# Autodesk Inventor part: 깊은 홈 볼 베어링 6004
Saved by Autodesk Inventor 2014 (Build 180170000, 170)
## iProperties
Created: 2026-04
Part Number: 깊은 홈 볼 베어링 6004
Material: 강철, 연강
Document SubType Name: Modeling
Designer: dg
Density: 7.86 g/cm^3
Appearance: 강철
Mass: 68.3136 g
Surface Area: 70.0178 cm^2
Volume: 8.6913 cm^3
Author: jhkim
Description: 깊은 그루브 볼 베어링
Creation Date: 2026-03-27
Sending System: Autodesk Inventor 2026
Preprocessor: ST-DEVELOPER v20.1
Author: dg
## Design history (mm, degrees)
node "깊은 홈 볼 베어링 60041"
body "Solid1"
node "Solid1_1"
node "Solid1_2"
node "Solid1_3"
node "Solid1_4"
node "Solid1_5"
node "Solid1_6"
node "Solid1_7"
node "Solid1_8"
node "Solid1_9"
node "Solid1_10"
node "기준1"
node "기준2"
node "기준3"
node "기준4"
node "기준5"
node "기준6"
node "기준7"
node "기준8"
node "기준9"
node "기준10"
node "기준11"
